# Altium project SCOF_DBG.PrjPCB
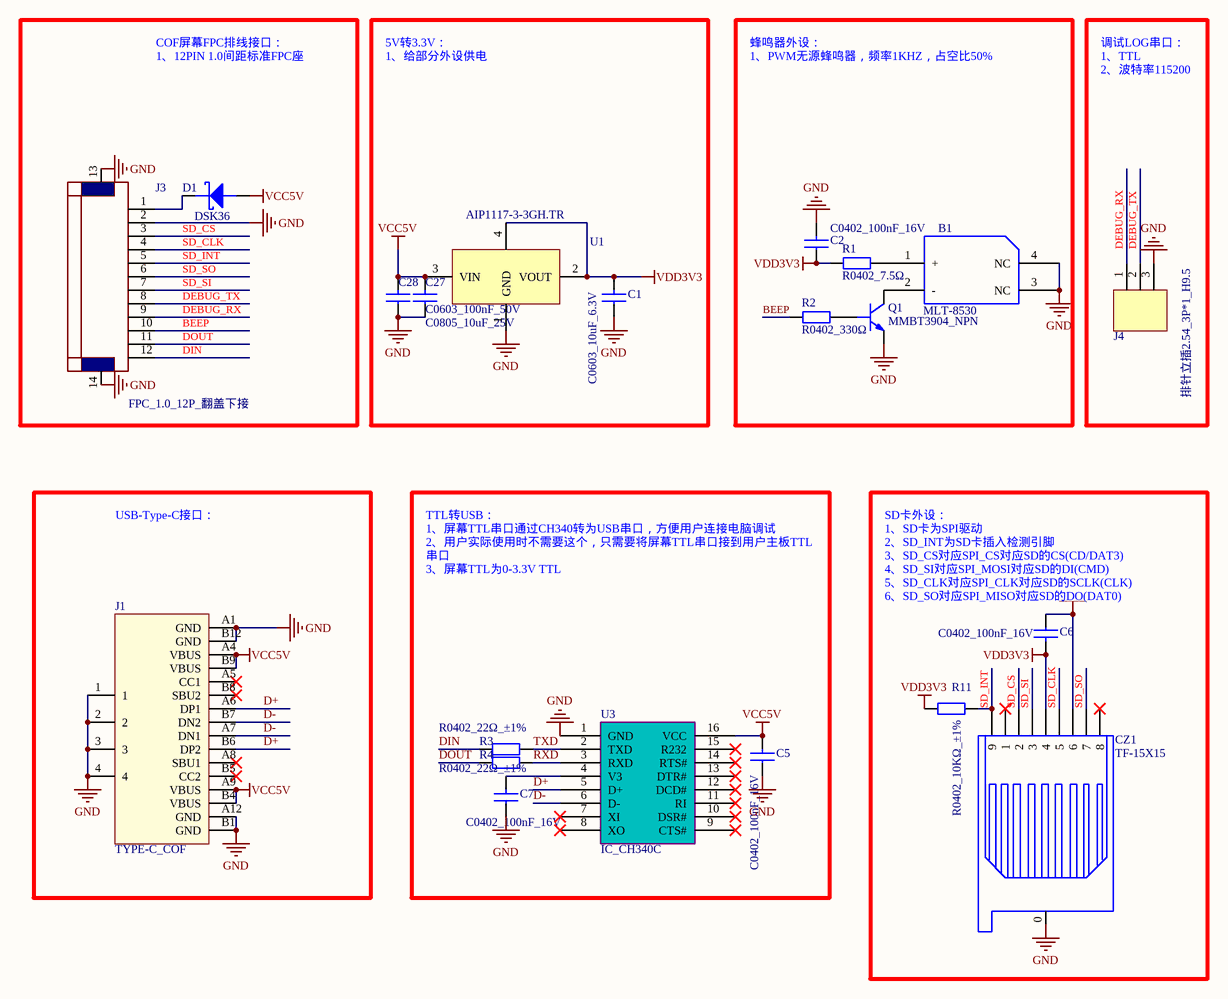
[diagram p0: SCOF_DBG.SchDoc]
2 sheets, 21 parts. Net scope: global (net labels, ports and power ports of the same name join across sheets).
Board file: SCOF_DBG.PcbDoc
Sheets:
  SCOF_DBG.SchDoc
  readme.SchDoc

## Sheet SCOF_DBG.SchDoc
size A3

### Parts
B1  MLT-8530  [BUZZER-SMD]
C1  C0603_10uF_6.3V  [0603C]
C2  C0402_100nF_16V  [0402C]
C5  C0402_100nF_16V  [0402C]
C6  C0402_100nF_16V  [0402C]
C7  C0402_100nF_16V  [0402C]
C27  C0603_100nF_50V  [0603C]
C28  C0805_10uF_25V  [0805C]
CZ1  TF-15X15  [T-F]
D1  DSK36  [SOD-123F]
J1  TYPE-C_COF  [TYPE-C_COF]
J3  FPC_1.0_12P_翻盖下接  [FFC-12S-1.0]
J4  排针立插2.54_3P*1_H9.5  [SIP2.54-3]
Q1  MMBT3904_NPN  [SOT-23]
R1  R0402_7.5Ω  [0402R]
R2  R0402_330Ω  [0402R]
R3  R0402_22Ω_±1%  [0402R]
R4  R0402_22Ω_±1%  [0402R]
R11  R0402_10KΩ_±1%  [0402R]
U1  AIP1117-3-3GH.TR  [SOT89]
U3  IC_CH340C  [SOIC-16]

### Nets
GND: B1.3(NC) B1.4(NC) C1.2 C2.1 C5.2 C6.2 C7.2 C27.2 C28.2 CZ1.0 CZ1.6 J1.1 J1.2 J1.3 J1.4 J1.A1(GND) J1.A12(GND) J1.B1(GND) J1.B12(GND) J3.2 J3.13 J3.14 J4.3 Q1.2(E) U1.1(GND) U3.1(GND)
VCC5V: C5.1 C27.1 C28.1 D1.1 J1.A4(VBUS) J1.A9(VBUS) J1.B4(VBUS) J1.B9(VBUS) U1.3(VIN) U3.16(VCC)
VDD3V3: C1.1 C2.2 C6.1 CZ1.4 R1.1 R11.1 U1.2(VOUT) U1.4
BEEP: J3.10 R2.1
D+: J1.A6(DP1) J1.B6(DP2) U3.5(D+)
D-: J1.A7(DN1) J1.B7(DN2) U3.6(D-)
DEBUG_RX: J3.9 J4.1
DEBUG_TX: J3.8 J4.2
DIN: J3.12 R3.1
DOUT: J3.11 R4.1
RXD: R4.2 U3.3(RXD)
SD_CLK: CZ1.5 J3.4
SD_CS: CZ1.2 J3.3
SD_INT: CZ1.9 J3.5 R11.2
SD_SI: CZ1.3 J3.7
SD_SO: CZ1.7 J3.6
TXD: R3.2 U3.2(TXD)
NetB1_1: B1.1(+) R1.2
NetB1_2: B1.2(-) Q1.3(C)
NetC7_1: C7.1 U3.4(V3)
NetD1_2: D1.2 J3.1
NetQ1_1: Q1.1(B) R2.2

Not connected (* = marked no-connect by the designer): CZ1 1* 8*; J1 A5(CC1)* A8(SBU1)* B5(CC2)* B8(SBU2)*; U3 7(XI)* 8(XO)* 9(CTS#)* 10(DSR#)* 11(RI)* 12(DCD#)* 13(DTR#)* 14(RTS#)* 15(R232)*

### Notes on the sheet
- 5V转3.3V：
  1、给部分外设供电
- 蜂鸣器外设：
  1、PWM无源蜂鸣器，频率1KHZ，占空比50%
- COF屏幕FPC排线接口：
  1、12PIN 1.0间距标准FPC座
- 调试LOG串口：
  1、TTL
  2、波特率115200
- USB-Type-C接口：
- TTL转USB：
  1、屏幕TTL串口通过CH340转为USB串口，方便用户连接电脑调试
  2、用户实际使用时不需要这个，只需要将屏幕TTL串口接到用户主板TTL串口
  3、屏幕TTL为0-3.3V TTL
- (near C6) SD卡外设：
  1、SD卡为SPI驱动
  2、SD_INT为SD卡插入检测引脚
  3、SD_CS对应SPI_CS对应SD的CS(CD/DAT3)
  4、SD_SI对应SPI_MOSI对应SD的DI(CMD)
  5、SD_CLK对应SPI_CLK对应SD的SCLK(CLK)
  6、SD_SO对应SPI_MISO对应SD的DO(DAT0)

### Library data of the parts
B1 = BUZZER_MLT-8530: 1.09.02.0001
C1 = C0603_10uF_6.3V: 1.02.02.0030
C2 = C0402_100nF_16V: 1.02.01.0026
C5-C7 = C0402_100nF_16V: 1.19.01.0004
C27 = C0603_100nF_50V: 1.02.01.0009
C28 = C0805_10uF_25V: 1.02.02.0009
CZ1 = TF-15X15: 1.07.01.0027
D1 = D_DSK36: 1.05.02.0014
J1 = TYPE-C_COF: 99
J4 = 排针立插2.54_3P*1_H9.5: 1.08.03.0012
Q1 = Q_MMBT3904_NPN: 1.05.04.0004
R1 = R0402_7.5Ω: 1.01.01.0011
R2 = R0402_330Ω: 1.01.01.0022
R3 R4 = R0402_22Ω_±1%: 1.01.05.0002
R11 = R0402_10KΩ_±1%: 1.01.05.0007
U1 = IC_SPX1117M3-L-3-3/TR: 1.07.02.0004
U3 = IC_CH340G/340C

## Sheet readme.SchDoc
size A4
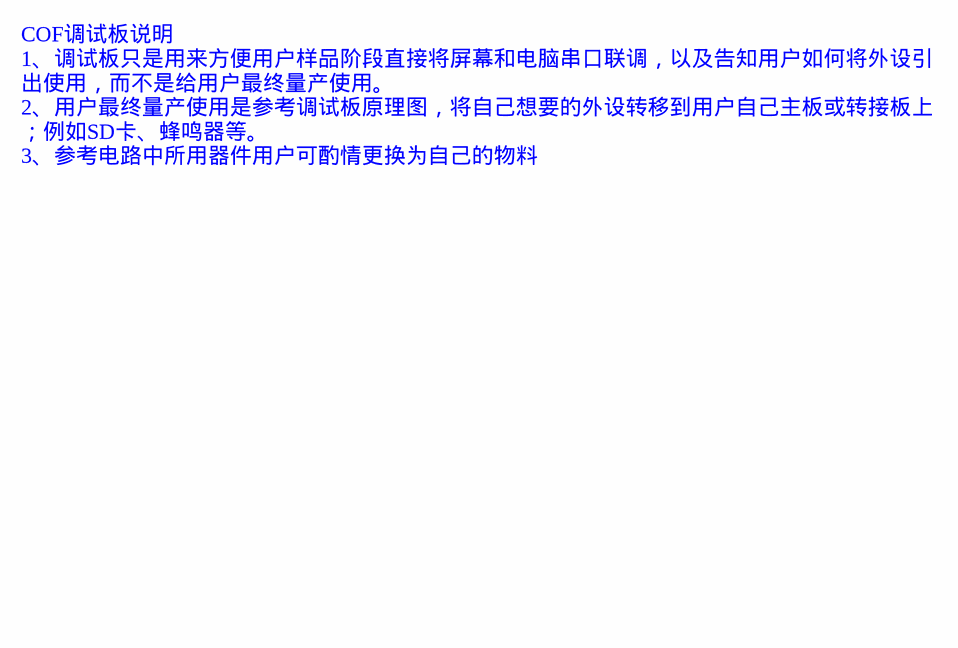
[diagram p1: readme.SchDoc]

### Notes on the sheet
- COF调试板说明
  1、调试板只是用来方便用户样品阶段直接将屏幕和电脑串口联调，以及告知用户如何将外设引出使用，而不是给用户最终量产使用。
  2、用户最终量产使用是参考调试板原理图，将自己想要的外设转移到用户自己主板或转接板上；例如SD卡、蜂鸣器等。
  3、参考电路中所用器件用户可酌情更换为自己的物料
